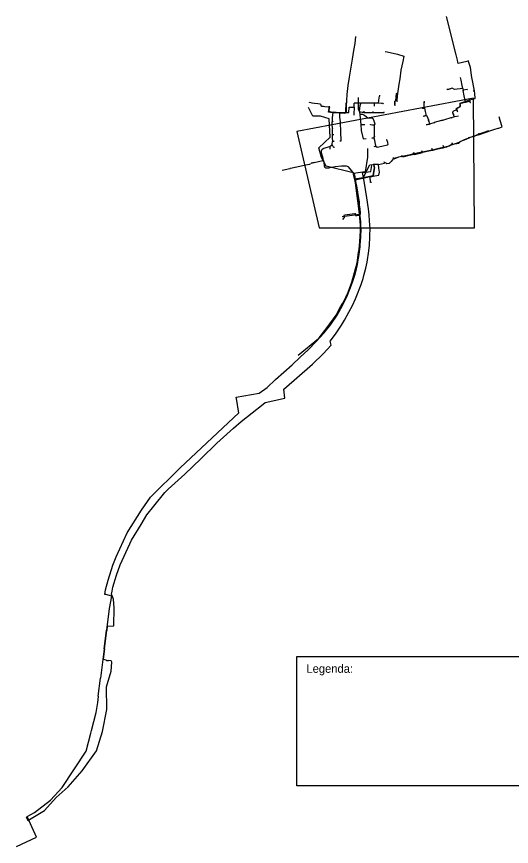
# Model space of a CAD drawing. Extents: x -791555 to -789832, y -979311 to -977823.
# Drawn here: x -791555 to -790668, y -979311 to -977823 of the extents above; entities that cross this region are included whole.
import ezdxf

# ---------------------------------------------------------------- set-up
doc = ezdxf.new("R2010")
doc.units = 0
for name, color, linetype in [('Vrstva 1', 7, 'Continuous'), ('Vrstva 2', 7, 'Continuous'), ('Vrstva 63', 7, 'Continuous')]:
    doc.layers.add(name, color=color, linetype=linetype)

msp = doc.modelspace()

# ---------------------------------------------------------------- linework, layer by layer
at = {"layer": 'Vrstva 1'}
for points in [[(-790754.8, -977952.2), (-790756, -977947.1), (-790757.9, -977937.5), (-790758.8, -977932.6)], [(-790875, -977974.5), (-790874.2, -977967.2), (-790873.4, -977961.5), (-790873.1, -977960.6)], [(-790754.8, -977952.2), (-790769.7, -977953.9), (-790773.6, -977951.9), (-790777.7, -977952.9), (-790781.3, -977953.9), (-790783.2, -977954.1)], [(-790781.3, -977953.9), (-790777.7, -977952.9)], [(-790754.8, -977952.2), (-790754.9, -977952.8), (-790754.3, -977955), (-790754.2, -977955.4)], [(-790754.9, -977952.8), (-790754.3, -977955)], [(-790746.2, -977954.5), (-790746.8, -977953.8), (-790753.7, -977955.2), (-790754.2, -977955.4)], [(-790754.1, -977956), (-790754.2, -977955.4)], [(-790749.9, -977976.8), (-790750.5, -977973.4), (-790752.1, -977965.2), (-790754.1, -977956)], [(-790753.7, -977955.2), (-790753, -977955)], [(-791030, -977977.1), (-791029.8, -977977), (-791025.5, -977977.8), (-791020.8, -977978.4), (-791014.8, -977979.3), (-791011, -977979.9), (-791009.8, -977980.5), (-791009.4, -977981.5), (-791009.6, -977983), (-791009.5, -977983.4), (-791008.3, -977983.7), (-791004.6, -977984.1), (-791002.5, -977984.3), (-790994.2, -977984.8), (-790993.9, -977985.5), (-790994.6, -977987.9), (-790995.1, -977991.6), (-790994.6, -977992.6), (-790993.6, -977993.3), (-790990.6, -977994.8), (-790988.1, -977995), (-790987.7, -977995.2)], [(-790974.9, -977996.1), (-790967, -977996.4), (-790965.3, -977995.6), (-790964.7, -977993.9), (-790964.1, -977978)], [(-790942.6, -977968.5), (-790942.7, -977972.6), (-790942.7, -977979), (-790942.7, -977981), (-790942.3, -977988.4), (-790941.3, -977991.9)], [(-790876, -977983.5), (-790876.3, -977983.6), (-790876.4, -977981), (-790876.8, -977977.1), (-790876.6, -977975.2), (-790875, -977974.5)], [(-790876.8, -977977.1), (-790876.4, -977981)], [(-790871.8, -977975.1), (-790875, -977974.5)], [(-790824.2, -977987.5), (-790824.1, -977982.5), (-790824.1, -977978.2), (-790824.2, -977975.8), (-790823.7, -977975.3)], [(-790824.2, -977975.8), (-790824.1, -977978.2)], [(-790770.7, -978003.1), (-790770.3, -978002.2), (-790771.5, -977998.8), (-790772.4, -977995.8), (-790772.5, -977994.3), (-790770.8, -977992.2), (-790766.5, -977990.4), (-790766.2, -977989.8), (-790766.4, -977988.5), (-790765.7, -977987.4), (-790759.3, -977984.6), (-790758.7, -977983.9), (-790758.9, -977981.5), (-790759.2, -977979.4), (-790753.3, -977977.2), (-790749.9, -977976.8)], [(-790749.9, -977976.8), (-790742.5, -977974.8), (-790741.6, -977977.6), (-790741.2, -977977.5)], [(-790988.1, -977995), (-790990.6, -977994.8), (-790993.6, -977993.3)], [(-790987.7, -977995.5), (-790989.2, -978004), (-790989.3, -978010.1)], [(-790987.7, -977995.5), (-790989.2, -978004)], [(-790986.8, -977994.9), (-790987.7, -977995.5)], [(-790987.7, -977995.2), (-790986.8, -977994.9)], [(-790987.7, -977995.5), (-790987.7, -977995.2)], [(-790974.9, -977996.1), (-790981.7, -977995.1), (-790983.1, -977995.2), (-790986.8, -977994.9)], [(-790981.7, -977995.1), (-790983.1, -977995.2)], [(-790974.9, -977994.5), (-790974.9, -977996.1)], [(-790941.3, -977991.9), (-790940, -977994.1)], [(-790940, -977994.1), (-790939.9, -977994.7), (-790939.5, -977998.5), (-790934.1, -977998.3), (-790930.3, -978000.9), (-790925.3, -978005), (-790920.9, -978005), (-790915.9, -978005.4), (-790913.9, -978012.1), (-790912.6, -978015.4), (-790913, -978017.2)], [(-790931.8, -977995.2), (-790935.5, -977995.1), (-790937.5, -977994.7), (-790939.1, -977994.7), (-790940, -977994.1)], [(-790939.9, -977994.7), (-790939.5, -977998.5)], [(-790931.8, -977995.2), (-790931.6, -977992.9)], [(-790931.8, -977995.2), (-790926.2, -977995.4), (-790920.2, -977995), (-790915.5, -977995.1)], [(-790915.5, -977995.1), (-790915.7, -977993.3)], [(-790915.5, -977995.1), (-790907.2, -977995.2), (-790897.8, -977995.5), (-790896.8, -977995.5), (-790896.1, -977995.1), (-790896, -977993.9)], [(-790827.1, -977988.2), (-790827.1, -977987.7), (-790824.2, -977987.5)], [(-790820.2, -978000.6), (-790820.4, -977998), (-790821.5, -977993.2), (-790822.6, -977987.7), (-790823.1, -977987.5), (-790824.2, -977987.5)], [(-790772.4, -977995.8), (-790771.5, -977998.8)], [(-790989.3, -978010.1), (-790989.5, -978013.1), (-790989.5, -978013.4)], [(-790989.3, -978010.1), (-790987.6, -978011.5), (-790987.5, -978012.1)], [(-790920.9, -978005), (-790915.9, -978005.4)], [(-790825.3, -978001.9), (-790820.2, -978000.6)], [(-790820.2, -978000.6), (-790825.3, -978001.9), (-790825.3, -978002.2)], [(-790820.2, -978000.6), (-790819.1, -978001.2), (-790816.3, -978008.5), (-790815.6, -978011.2), (-790814.7, -978016.2)], [(-790815.6, -978011.2), (-790816.3, -978008.5)], [(-790790.7, -978008.9), (-790792.7, -978009.4), (-790799.5, -978011.5), (-790806.2, -978013.4)], [(-790792.7, -978009.4), (-790790.7, -978008.9)], [(-790790.7, -978008.9), (-790787, -978007.8)], [(-790790.7, -978008.9), (-790790.5, -978009.7)], [(-790787, -978007.8), (-790785.1, -978007.3), (-790777.4, -978005.1), (-790775.8, -978004.5), (-790775.4, -978004.5)], [(-790777.4, -978005.1), (-790775.8, -978004.5)], [(-790775.4, -978004.5), (-790770.7, -978003.1)], [(-790775.4, -978004.5), (-790775.3, -978005.3)], [(-790770.7, -978003.1), (-790768.9, -978002.6), (-790762.3, -978001)], [(-790989.5, -978013.4), (-790989.6, -978017.2), (-790989, -978022.6), (-790988.7, -978024.6)], [(-790988.7, -978024.6), (-790988.8, -978026)], [(-790920.5, -978017.4), (-790920.5, -978016.9), (-790919.9, -978016.9), (-790916.8, -978017.1), (-790913, -978017.2)], [(-790919.9, -978016.9), (-790916.8, -978017.1)], [(-790914.1, -978040.8), (-790913, -978037.8), (-790913, -978017.2)], [(-790814.7, -978016.2), (-790817.4, -978017), (-790819.5, -978017.2), (-790820.7, -978017.6)], [(-790817.4, -978017), (-790814.7, -978016.2)], [(-790814.7, -978016.2), (-790812.1, -978015.2), (-790808, -978013.9), (-790806.2, -978013.4)], [(-790808, -978013.9), (-790806.2, -978013.4)], [(-790806.2, -978013.4), (-790805.9, -978014.2)], [(-790988.9, -978034.8), (-790989, -978040.7), (-790988.3, -978047.5)], [(-790988.8, -978026), (-790988.9, -978034.8)], [(-790988.9, -978034.8), (-790986.3, -978034.6)], [(-790913, -978037.8), (-790914.1, -978040.8)], [(-790743.1, -978040.9), (-790743.9, -978039.6)], [(-790726.2, -978034.1), (-790732.4, -978036.8), (-790733.5, -978037.5), (-790743.1, -978040.9)], [(-790733.5, -978037.5), (-790732.4, -978036.8)], [(-790726.2, -978034.1), (-790726.7, -978033.1)], [(-790724.4, -978033.3), (-790726.2, -978034.1)], [(-790708.6, -978028.1), (-790716.9, -978031.1), (-790724.4, -978033.3)], [(-790993.2, -978056.2), (-790989.5, -978053.2)], [(-790989.5, -978053.2), (-790989.3, -978052.8)], [(-790989.3, -978052.8), (-790988.8, -978052.1), (-790988.3, -978047.5)], [(-790984.9, -978057.9), (-790984.9, -978058.1), (-790986.2, -978058.1), (-790986.1, -978057.8), (-790986.7, -978057.6), (-790989.3, -978052.8)], [(-790985.5, -978047.4), (-790988.3, -978047.5)], [(-790914.1, -978040.8), (-790917.7, -978041.4), (-790918, -978041.2)], [(-790917.7, -978041.4), (-790914.1, -978040.8)], [(-790914.1, -978040.8), (-790913.2, -978045.1)], [(-790913.2, -978045.1), (-790912.5, -978048.8), (-790911.2, -978054.2), (-790910.6, -978055.8)], [(-790910.6, -978055.8), (-790908.6, -978057.3), (-790900.2, -978055.6), (-790889.8, -978053), (-790888.9, -978052.4), (-790889.4, -978049.1), (-790890.9, -978044), (-790891.7, -978044.2)], [(-790774, -978053.3), (-790774.4, -978052.7), (-790779.3, -978055.4), (-790797.5, -978060), (-790809.6, -978062.8), (-790833.8, -978067.8), (-790842.2, -978069.3), (-790851.7, -978071.6), (-790869.9, -978075.6)], [(-790788.8, -978058.4), (-790789.8, -978054.5)], [(-790774, -978053.3), (-790779.2, -978054.9), (-790784.2, -978057.2), (-790788.8, -978058.4)], [(-790773.3, -978052.7), (-790774.1, -978050.1), (-790773.7, -978049.9)], [(-790773.3, -978052.7), (-790774, -978053.3)], [(-790773.3, -978052.7), (-790765.9, -978050.4), (-790761.4, -978048.6), (-790759.2, -978047.5), (-790755.2, -978045.2), (-790751.8, -978044.4), (-790743.1, -978040.9)], [(-790759.2, -978047.5), (-790755.2, -978045.2)], [(-791005.5, -978077.8), (-791008.4, -978067.7), (-791008.5, -978063.8), (-791007.3, -978060.9), (-791004.3, -978059.1), (-790993.2, -978056.2)], [(-790993.2, -978056.2), (-790993, -978061)], [(-790910.6, -978055.8), (-790914.3, -978056.9)], [(-790841.5, -978070.3), (-790851.6, -978072.6), (-790863.1, -978075.4), (-790864.1, -978072.1)], [(-790841.5, -978070.3), (-790844.1, -978067.4)], [(-790841.5, -978070.3), (-790834.1, -978068.6), (-790831.3, -978068.3)], [(-790831.3, -978068.3), (-790827.3, -978067.1)], [(-790827.3, -978067.1), (-790828, -978063.7)], [(-790809.2, -978063.2), (-790815.7, -978064.8), (-790823.8, -978066.4), (-790827.3, -978067.1)], [(-790809.2, -978063.2), (-790810.1, -978059.6)], [(-790790.8, -978058.9), (-790802.3, -978061.7), (-790809.2, -978063.2)], [(-790788.8, -978058.4), (-790790.8, -978058.9)], [(-791021.1, -978084.6), (-791026.5, -978085.9), (-791013.8, -978082.9), (-791006.1, -978081.1), (-791004.7, -978081.3)], [(-791013.8, -978082.9), (-791006.1, -978081.1)], [(-791004.7, -978081.3), (-791005.5, -978077.8)], [(-791004.7, -978081.3), (-791004.3, -978083.6), (-791003.3, -978091.3), (-791002.2, -978093.1), (-791000.2, -978094.2), (-790998.9, -978094.7), (-790994.6, -978094.6), (-790993.2, -978094), (-790984, -978092.3), (-790972.2, -978091.1), (-790963.8, -978090.8), (-790962.2, -978091.5)], [(-791004.3, -978083.6), (-791003.3, -978091.3)], [(-790895.5, -978085.1), (-790895.8, -978083.4)], [(-790895.2, -978086), (-790895.5, -978085.1), (-790895.8, -978083.4)], [(-790879.6, -978078), (-790883.3, -978083.2), (-790886.7, -978086.4), (-790891, -978087), (-790893, -978085.6), (-790895.2, -978086)], [(-790879.9, -978075.8), (-790879.6, -978077), (-790878.5, -978078.7)], [(-790869.9, -978075.6), (-790879.6, -978078)], [(-790869.9, -978075.6), (-790878.5, -978078.7)], [(-791078.9, -978098.4), (-791065, -978095.4), (-791064.4, -978095.4), (-791063.6, -978095), (-791055.7, -978093.3)], [(-791055.8, -978093.1), (-791055.7, -978093.3)], [(-791055.7, -978093.3), (-791041.6, -978090.3), (-791033.1, -978088.5)], [(-791033.2, -978088.2), (-791033.1, -978088.5)], [(-791033.1, -978088.5), (-791028.8, -978087.6), (-791028.4, -978087.1)], [(-791028.5, -978086.5), (-791028.4, -978087.1)], [(-790962.2, -978091.5), (-790961.2, -978091.8), (-790960.2, -978092.6), (-790949.8, -978105.9), (-790949.3, -978106.8), (-790947.1, -978118.7), (-790944.9, -978130.4), (-790942.6, -978146)], [(-790918.7, -978120.9), (-790920.1, -978121), (-790920.9, -978110.3), (-790912.5, -978108.7), (-790905.2, -978107.8), (-790904.1, -978102.1), (-790905.2, -978094.8), (-790906.2, -978088.4), (-790895.2, -978086)], [(-790913.5, -978092.6), (-790913.2, -978093.7), (-790914.9, -978104.4)], [(-790914.6, -978087.7), (-790913.5, -978092.6)], [(-790905.2, -978094.8), (-790906.2, -978088.4)], [(-790904.1, -978102.1), (-790905.2, -978094.8)], [(-790941.3, -978167.1), (-790946, -978130.7), (-790948.1, -978114.8)], [(-790945.5, -978114.3), (-790933.3, -978112.1)], [(-790914.9, -978104.4), (-790915.7, -978108.8), (-790933.3, -978112.1)], [(-790942.6, -978146), (-790940.7, -978155.1), (-790940.6, -978161), (-790939.2, -978167.6), (-790939, -978175.6), (-790939, -978177.5), (-790939.5, -978178.4), (-790940.6, -978179)], [(-790940, -978177.2), (-790941.3, -978167.1)], [(-790940.1, -978173.8), (-790941, -978165.2)], [(-790939.2, -978167.6), (-790939, -978175.6)], [(-791050.1, -978429.9), (-791013.8, -978400.1), (-791012.5, -978398.8), (-790997.8, -978380.7), (-790982.1, -978358.5), (-790974, -978343.6), (-790970.1, -978337.1), (-790964, -978325.2), (-790962.4, -978321.8), (-790958.1, -978310.9), (-790953.6, -978299.1), (-790944.3, -978264.9), (-790941.6, -978246), (-790940.8, -978241), (-790940, -978233.3), (-790939.4, -978227.1), (-790938.5, -978207.1), (-790938.3, -978197.1), (-790940, -978177.2)], [(-790984.1, -978363.2), (-790981.7, -978359.7), (-790976.4, -978350.2), (-790969.4, -978337.6), (-790966.2, -978331.3), (-790961.4, -978321.5), (-790959.8, -978317.7), (-790956.7, -978309.5), (-790952.8, -978299.4), (-790948.7, -978286.7), (-790945.5, -978275.4), (-790943.7, -978267.5), (-790942.4, -978259.4), (-790941.4, -978253.6), (-790939.9, -978244.2), (-790938.9, -978235.7), (-790939.6, -978233), (-790939.1, -978227.5), (-790938.3, -978214), (-790937.9, -978202.3), (-790937.9, -978190.5), (-790938.6, -978180.9), (-790939.2, -978179.4), (-790940.6, -978179)], [(-790970.2, -978187.1), (-790967.4, -978184.3), (-790967.1, -978183.3), (-790967.6, -978179.9), (-790967, -978178.9), (-790957.3, -978177.5), (-790953.3, -978176.8), (-790948.2, -978176.2), (-790947.7, -978176.2), (-790947.4, -978176.6), (-790947.1, -978179.6), (-790946.8, -978179.8), (-790944.6, -978179.6), (-790940.6, -978179)], [(-790944.6, -978179.6), (-790940.6, -978179)], [(-790938, -978224.3), (-790937.9, -978221.9)]]:
    msp.add_lwpolyline(points, dxfattribs=at)
msp.add_lwpolyline([(-791052.5, -978969.9), (-789832.5, -978969.9), (-789832.5, -979202), (-791052.5, -979202)], close=True, dxfattribs=at)
at = {"layer": 'Vrstva 2'}
for points in [[(-790759.2, -977985.1), (-790759.6, -977978.8), (-790750.7, -977975.6), (-790742.9, -977972.7), (-790732.7, -977970), (-790733, -977961.1), (-790733.8, -977956.2), (-790734.7, -977950.6), (-790737.6, -977937.9), (-790738.8, -977932.8), (-790739.1, -977928.5), (-790741.1, -977914.7), (-790742.8, -977909.5), (-790743.7, -977905.5), (-790744.6, -977902.9), (-790747.8, -977903.8), (-790763, -977907.5), (-790763.6, -977904.9), (-790764.4, -977901.6), (-790765.4, -977896.5), (-790766.6, -977891.9), (-790771.2, -977873.5), (-790777.9, -977846.8), (-790783.8, -977823.4)], [(-790947, -977859.1), (-790948.6, -977871.3), (-790950.6, -977884.4), (-790953, -977899.8), (-790955.6, -977913.8), (-790958.3, -977932.1), (-790961.1, -977947), (-790963, -977963.2), (-790963.8, -977984.3), (-790964.2, -977994.9), (-790965.7, -977996.4), (-790975.7, -977995.8), (-790985.6, -977995.6), (-790987.3, -977995.5), (-790992.2, -977995.3), (-790995.6, -977994.9), (-790993.6, -977983.9)], [(-790894, -977886.1), (-790890.6, -977886.8), (-790871.7, -977890.6), (-790860.6, -977894.2), (-790862.4, -977903.6), (-790865.8, -977919.3), (-790867.7, -977934.9), (-790869.3, -977944.7), (-790872.2, -977965.5), (-790872.8, -977974.8)], [(-790904.3, -977964.4), (-790904.4, -977965.7), (-790904.6, -977966.7), (-790905.3, -977969.1), (-790906.3, -977978.5), (-790913.7, -977978.8)], [(-790736.2, -977956.7), (-790733.8, -977956.2)], [(-790949.9, -977985.9), (-790949.8, -977978.3)], [(-790949.9, -977985.9), (-790949.8, -977978.3)], [(-790897.8, -977977.7), (-790898.8, -977979.5), (-790899.8, -977979.4), (-790939.1, -977978.5), (-790949.8, -977978.3)], [(-790897.8, -977977.7), (-790898.8, -977979.5), (-790899.8, -977979.4), (-790939.1, -977978.5), (-790949.8, -977978.3)], [(-790913.7, -977978.8), (-790923, -977978.6), (-790937.7, -977978.3), (-790938.9, -977981.7), (-790939.5, -977983.1), (-790940.2, -977987.7), (-790940.4, -977992.7), (-790939.6, -977998.1), (-790939.1, -978006.1), (-790937.9, -978016.9)], [(-790913.7, -977978.8), (-790913.7, -977983.9)], [(-790872.8, -977974.8), (-790871.9, -977974.8)], [(-790742.9, -977972.7), (-790741.6, -977977.6)], [(-790950.6, -978106.2), (-790950.9, -978104.6), (-790951.2, -978103.3), (-790999.8, -978091.5), (-791008, -978076), (-791013.1, -978058.6), (-790992.6, -978039.3), (-790994.4, -978006.8), (-791009.9, -978001.7), (-791023.9, -978001.7), (-791031.5, -977986.1)], [(-790986.1, -977994.1), (-790986.1, -977994.6), (-790965.7, -977995.3), (-790958.9, -977995.5), (-790958.8, -977985.6), (-790949.9, -977985.9)], [(-790986.1, -977994.1), (-790986.1, -977994.6), (-790965.7, -977995.3), (-790958.9, -977995.5), (-790958.8, -977985.6), (-790949.9, -977985.9)], [(-790985.5, -977994.3), (-790985.6, -977995.6)], [(-790975.7, -977995.8), (-790975.7, -977998.4), (-790975.9, -978003.6), (-790975, -978011.7), (-790974.9, -978013.5), (-790974.2, -978029.6), (-790973.5, -978046.5), (-790975.1, -978046.7)], [(-790949.9, -977985.9), (-790950.1, -977998.9), (-790950, -978000)], [(-790949.9, -977985.9), (-790950.1, -977998.9), (-790950, -978000)], [(-790759.2, -977985.1), (-790766, -977988.6), (-790765.1, -977992.5)], [(-790763.6, -977994.8), (-790765.1, -977992.5)], [(-790773.5, -978052.1), (-790761.9, -978050.2), (-790759, -978047.3), (-790755.2, -978045.2), (-790751.5, -978043.9), (-790734.1, -978037.3), (-790725, -978034.6), (-790716.5, -978031.5), (-790699.3, -978025.7), (-790691.1, -978023.4), (-790689.9, -978023.1), (-790683.9, -978021.2), (-790687.9, -978009.8), (-790689.3, -978003.3)], [(-790937.9, -978016.9), (-790930.3, -978016.8)], [(-790937.9, -978016.9), (-790936.8, -978027.5), (-790933.5, -978042.6), (-790928.1, -978041.6)], [(-790725.7, -978032.7), (-790725, -978034.6)], [(-790774.4, -978052.7), (-790773.5, -978052.1)], [(-790774.2, -978050.2), (-790773.5, -978052.1)], [(-790925.5, -978059.9), (-790925.7, -978075.5), (-790929.7, -978101.4), (-790950.9, -978104.6)], [(-790842.8, -978067.2), (-790842.2, -978069.3)], [(-790810.3, -978059.7), (-790809.6, -978062.8)], [(-790879.8, -978075.8), (-790879.6, -978078)], [(-791537.8, -979257.7), (-791534.9, -979264.1), (-791505.2, -979246.3), (-791484.3, -979222.9), (-791462.7, -979203.6), (-791437.8, -979174.9), (-791412.1, -979139.1), (-791401.1, -979104.5), (-791393.5, -979064.9), (-791394, -979024.3), (-791385.7, -978996.4), (-791384.6, -978980.1), (-791385.6, -978978.2), (-791390.5, -978977.2), (-791391.1, -978977.8), (-791391.8, -978978), (-791392.6, -978978.1), (-791393.6, -978977.7), (-791394.2, -978977.1), (-791394.4, -978976.5), (-791399.4, -978975.5), (-791396.9, -978956.7), (-791397.6, -978956.4), (-791393.5, -978923.5), (-791393, -978923.4), (-791392.1, -978915.7), (-791380.8, -978915.3), (-791379.9, -978883.2), (-791381.1, -978867.2), (-791384.8, -978858.6), (-791383.8, -978853.2), (-791382.4, -978845.9), (-791376.2, -978824.5), (-791369.7, -978806), (-791352.3, -978768), (-791349.3, -978761.7), (-791332, -978733.7), (-791321.8, -978716.5), (-791309.2, -978700.7), (-791289.5, -978676.2), (-791283.3, -978670.3), (-791253.6, -978643.2), (-791224.6, -978615.7), (-791195.8, -978587.9), (-791166.1, -978561.2), (-791152.6, -978549.1), (-791113, -978518), (-791109.3, -978514.7), (-791074.1, -978507.3), (-791075.9, -978491.1), (-791024.6, -978446.4), (-791005.5, -978427.6), (-790990.7, -978412), (-790991.2, -978409.8), (-790992.5, -978404.8), (-790983.4, -978392.6), (-790978.3, -978385.2), (-790972.5, -978376.4), (-790967.1, -978367.4), (-790959.2, -978353.3), (-790952.6, -978341), (-790947.2, -978329.2), (-790943.5, -978320.2), (-790939.3, -978309.7), (-790937.2, -978303.7), (-790933.7, -978292.7), (-790932, -978287.4), (-790928.9, -978274.4), (-790926.4, -978263.5), (-790925.6, -978259.2), (-790923.8, -978247.2), (-790922.3, -978233.8), (-790922.1, -978230.1), (-790921.6, -978221.7), (-790921.4, -978215.4), (-790921.2, -978203.9), (-790922, -978189.6), (-790922.8, -978178.9), (-790924, -978168.1), (-790926.7, -978148.2), (-790931.8, -978118.6), (-790934.5, -978102.5), (-790919.5, -978101), (-790917.7, -978090.1)], [(-790991.2, -978409.8), (-790992.5, -978404.8), (-790983.4, -978392.6), (-790978.3, -978385.2), (-790972.5, -978376.4), (-790967.1, -978367.4), (-790959.2, -978353.3), (-790952.6, -978341), (-790947.2, -978329.2), (-790943.5, -978320.2), (-790939.3, -978309.7), (-790937.2, -978303.7), (-790933.7, -978292.7), (-790932, -978287.4), (-790928.9, -978274.4), (-790926.4, -978263.5), (-790925.6, -978259.2), (-790923.8, -978247.2), (-790922.3, -978233.8), (-790922.1, -978230.1), (-790921.6, -978221.7), (-790921.4, -978215.4), (-790921.2, -978203.9), (-790922, -978189.6), (-790922.8, -978178.9), (-790924, -978168.1), (-790926.7, -978148.2), (-790931.8, -978118.6), (-790934.5, -978102.5), (-790919.5, -978101), (-790917.7, -978090.1)], [(-790933.3, -978112.1), (-790915.7, -978108.8), (-790914.9, -978104.4), (-790913.2, -978093.7), (-790913.5, -978092.6), (-790914.6, -978087.7)], [(-790933.3, -978112.1), (-790921.3, -978089.2), (-790917.2, -978088.3)], [(-790906.2, -978088.4), (-790915.3, -978088.6), (-790915.5, -978088)], [(-790947.7, -978117.8), (-790950.6, -978106.2)], [(-790946.8, -978114.6), (-790948.1, -978114.8), (-790946, -978130.7)], [(-790947.7, -978117.8), (-790945.3, -978115.1), (-790925.7, -978111.3)], [(-790933.3, -978112.1), (-790945.5, -978114.3), (-790946.8, -978114.6)], [(-791555.2, -979310.5), (-791519.7, -979293.9), (-791522.1, -979288.6), (-791536.1, -979256.8), (-791523.2, -979249.8), (-791494.1, -979227.9), (-791473.6, -979204.7), (-791430.6, -979140.1), (-791422, -979107.3), (-791420.8, -979102.9), (-791412.4, -979070.6), (-791409.3, -979052.6), (-791408, -979041.7), (-791408.7, -979041.4), (-791404.7, -979009), (-791404.2, -979008.8), (-791399.9, -978975.7), (-791397.4, -978956.9), (-791398, -978956.6), (-791393.7, -978923.1), (-791393.3, -978923.1), (-791388.8, -978884.1), (-791384.6, -978861.9), (-791395.3, -978859.3), (-791397, -978858.9), (-791395.5, -978850.8), (-791391, -978833.5), (-791382.5, -978806.5), (-791376.7, -978791.3), (-791356.8, -978748.3), (-791331, -978707.8), (-791314.9, -978684.9), (-791261.9, -978632.2), (-791156.8, -978533.4), (-791157.3, -978530.6), (-791160.4, -978511.1), (-791160.8, -978508.5), (-791161.3, -978505.5), (-791120.1, -978498), (-791105.8, -978487.9), (-791090.7, -978473.9), (-791061, -978447.4), (-791046.3, -978434), (-791031.9, -978420.4), (-791017.7, -978405.8), (-791003.9, -978390.8), (-790991.6, -978375.1), (-790980.1, -978358.5), (-790970.3, -978341), (-790961.3, -978322.6), (-790954.2, -978303.9), (-790948.5, -978284.7), (-790943.5, -978265.2), (-790939.8, -978245.6), (-790938.1, -978225.6), (-790937.1, -978205.4), (-790939, -978185.1), (-790940.1, -978173.8), (-790941, -978165.2), (-790941.5, -978157.1), (-790943.2, -978145.4), (-790946.4, -978125.6), (-790947.7, -978117.8)], [(-790946, -978130.7), (-790941.3, -978167.1), (-790940, -978177.2)], [(-790971.2, -978181.9), (-790940, -978177.2)], [(-790940, -978233.3), (-790939.4, -978227.1), (-790938.5, -978207.1), (-790938.3, -978197.1), (-790940, -978177.2)]]:
    msp.add_lwpolyline(points, dxfattribs=at)
at = {"layer": 'Vrstva 63'}
msp.add_lwpolyline([(-791052.5, -978029.2), (-791012.5, -978202), (-790733.7, -978202), (-790735.6, -977969.6), (-791052.5, -978029.2)], close=True, dxfattribs=at)

# ---------------------------------------------------------------- texts
at = {"layer": 'Vrstva 1'}
msp.add_text('Legenda:', height=15, dxfattribs=at).set_placement((-791035.3, -978999.4))

doc.saveas('drawing.dxf')
